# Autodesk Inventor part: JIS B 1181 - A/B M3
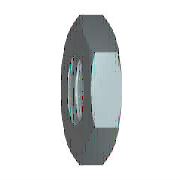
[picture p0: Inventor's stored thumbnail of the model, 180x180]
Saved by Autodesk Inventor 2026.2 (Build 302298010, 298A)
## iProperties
Created: 2025-01
Part Number: JIS B 1181 - A/B M3
Material: 강철, 연강
Description: 6각 가는 너트 - 이중 모따기
Document SubType Name: Modeling
Standard: JIS B 1181
Designer: work
Standard Revision: 2014
Standards Organization: JIS
Language: ko-KR
Size Designation: A/B M3
Categories: <MemberInstance><Categories><Category DisplayName="조임쇠" InternalName="e4da775c-781d-43d5-af7c-5136215cf5a6" Mnemonic="FSTN"><Category DisplayName="너트" InternalN
Density: 7.85 g/cm^3
Appearance: 반연마
IsCustomPart: 1
Author: work
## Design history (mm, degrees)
body "Solid1"
workaxis "Work Axis1"
workplane "Work Plane1"
sketch "스케치1"
  geometry: L1 (-3.175, 0)-(-1.588, 2.75); L2 (-1.588, 2.75)-(1.588, 2.75); L3 (1.588, 2.75)-(3.175, 0); L4 (3.175, 0)-(1.588, -2.75); L5 (1.588, -2.75)-(-1.588, -2.75); L6 (-1.588, -2.75)-(-3.175, 0); 2 further points
  constraints: 12 end point, 1 coincident, 1 horizontal, 11 other
  dimensions: "d0" = 6.35085 distance of L3.end L1.start (= 1.1547 x SW)
extrude "본체" new body sketch "스케치1" distance "d1" = 1.8 (= KOH); taper "d2" = 0 deg
revolve "모따기1" stored, may be unused: angle "d7" = 90 deg
sketch "스케치3"
  geometry: A1 r 2.75 centre (0, 0) between (-1.375, -2.382) and (1.375, -2.382) reference; 1 further point
  constraints: 1 coincident
hole "스레드" sketch "스케치3" diameter "d25" = 2.459; stored, may be unused: countersink angle "d29" = 82 deg, drill point angle "d31" = 118 deg; dims "d26" = 6, "d27" = 4, "d28" = 2, "d30" = 8
chamfer "모따기2" distance "d8" = 0.27063 (= -0.5 x GD1 + 0.5 x NND); stored, may be unused: angle "d9" = 30 deg, second distance "d40" = 0.27063 (= -0.5 x GD1 + 0.5 x NND)
chamfer "모따기3" distance "d10" = 0.27063 (= -0.5 x GD1 + 0.5 x NND); stored, may be unused: angle "d11" = 30 deg, second distance "d41" = 0.27063 (= -0.5 x GD1 + 0.5 x NND)
sketch "스케치2"
  geometry: L1 (0, 1.588)-(0, 3.175) reference; L2 (0, 3.175)-(1.8, 3.175) reference; L3 (1.8, 1.588)-(1.8, 3.175) reference; L4 (-0.36, 0)-(2.16, 0) reference; L5 (0.246, 3.175)-(0, 2.75); L6 (1.554, 3.175)-(1.8, 2.75)
  constraints: 4 end point, 4 point on line
  dimensions: "d3" = 30 deg angle of L1 L5 (= ANG1); "d4" = 30 deg angle of L3 L6 (= ANG2); "d5" = 5.5 diameter of L5.end L4 (= SW0); "d6" = 5.5 diameter of L6.end L4 (= SW01)
other parameters: "ANG1" = 30 deg [user parameter; used in 1 equation term], "ANG2" = 30 deg [user parameter; used in 1 equation term], "NND" = 3 [user parameter; used in 4 equation terms], "KOH" = 1.8 [user parameter; used in 1 equation term], "SW" = 5.5 [user parameter; used in 4 equation terms], "SW0" = 5.5 (= SW) [user parameter; used in 1 equation term], "SW01" = 5.5 (= SW) [user parameter; used in 1 equation term], "GD1" = 2.45873 (computed from THREADDIA, PTC, TOA) [user parameter; used in 4 equation terms], "d13" = 0, "d14" = 0, "d39" = 0, "d42" = 0, "GUL" = 0.27063 (= 0.541266 x PTC) [user parameter], "THREADDIA" = 3 [user parameter; used in 1 equation term], "TOA" = 30 deg [user parameter; used in 1 equation term], "PTC" = 0.5 [user parameter; used in 4 equation terms], "E0" = 6.3525 (= 1.155 x SW) [user parameter], "GAL" = 0.27063 (= 0.541266 x PTC) [user parameter]
